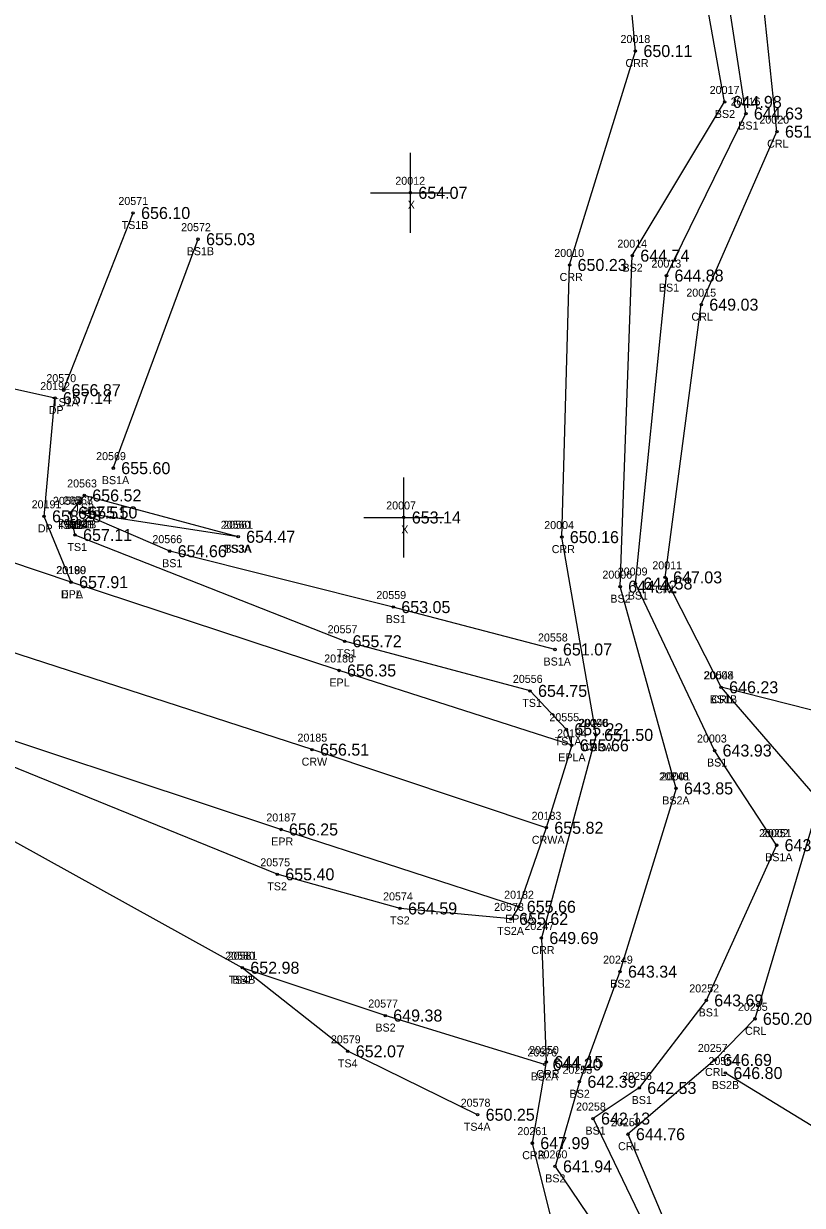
# Model space of a CAD drawing. Extents: x 1655675 to 1657082, y 1004080 to 1005193.
# Drawn here: x 1656296.6 to 1656393.9, y 1004582.5 to 1004730.1 of the extents above; entities that cross this region are included whole.
import ezdxf

# ---------------------------------------------------------------- set-up
doc = ezdxf.new("R2010")
doc.units = 0
for name, color, linetype in [('RD_DTM_BkLn1', 7, 'Continuous'), ('RD_DTM_BkLn2', 7, 'Continuous'), ('RD_DTM_BkLn_txCode', 7, 'Continuous'), ('RD_EX_Driveway', 7, 'Continuous'), ('RD_EX_Driveway_txCode', 7, 'Continuous'), ('RD_EX_H2O', 7, 'Continuous'), ('RD_EX_H2O_txCode', 7, 'Continuous'), ('RD_EX_Misc', 7, 'Continuous'), ('RD_EX_Misc_txCode', 7, 'Continuous'), ('RD_EX_Road', 7, 'Continuous'), ('RD_EX_Road_txCode', 7, 'Continuous'), ('RD_EX_TX_Driveway_ELEV', 7, 'Continuous'), ('RD_EX_TX_H2O_ELEV', 7, 'Continuous'), ('RD_EX_TX_Misc_ELEV', 7, 'Continuous'), ('RD_EX_TX_Road_ELEV', 7, 'Continuous'), ('RD_HC_Survey_ELEV', 7, 'Continuous'), ('RD_HC_Survey_txCode', 7, 'Continuous'), ('RD_SMD_Locator', 7, 'Continuous')]:
    doc.layers.add(name, color=color, linetype=linetype)

msp = doc.modelspace()

# ---------------------------------------------------------------- linework, layer by layer
at = {"layer": 'RD_DTM_BkLn1'}
for points in [[(1656361.94, 1004629.69), (1656332.67, 1004639.45), (1656283.94, 1004655.24), (1656235.41, 1004671.18), (1656186.64, 1004687.32), (1656138.18, 1004703.47), (1656089.58, 1004719.78), (1656041.19, 1004735.88), (1655992.79, 1004752.04), (1655944.27, 1004768.13), (1655895.76, 1004783.85), (1655847.16, 1004799.72), (1655798.63, 1004815.7), (1655750.32, 1004831.65), (1655701.73, 1004847.83)], [(1656364.44, 1004642), (1656365.12, 1004639.99), (1656361.94, 1004629.69), (1656358.5, 1004619.83), (1656357.54, 1004618.31)]]:
    msp.add_lwpolyline(points, dxfattribs=at)
at = {"layer": 'RD_DTM_BkLn2'}
for p, q in [((1656301.62, 1004684.35), (1656310.3, 1004706.48)), ((1656307.82, 1004674.61), (1656318.42, 1004703.21)), ((1656323.43, 1004666.04), (1656303.7, 1004669.08))]:
    msp.add_line(p, q, dxfattribs=at)
for points in [[(1656390.72, 1004627.52), (1656382.97, 1004639.34), (1656373.07, 1004660.2), (1656376.96, 1004698.66), (1656386.88, 1004718.9), (1656381.04, 1004756.9), (1656388.26, 1004792), (1656390.04, 1004832.88), (1656413.02, 1004880.46), (1656422.17, 1004937.24), (1656409.91, 1004961.28), (1656410.07, 1005007.08), (1656404.22, 1005036.82), (1656413.87, 1005085.9), (1656434.1, 1005133.63), (1656432.64, 1005179.28)], [(1656378.15, 1004634.61), (1656371.17, 1004659.81), (1656372.69, 1004701.15), (1656384.23, 1004720.35), (1656377.68, 1004756.93), (1656385.56, 1004794.36), (1656385.16, 1004833.8), (1656408.06, 1004879.84), (1656418.86, 1004937.52), (1656406.15, 1004960.8), (1656407.08, 1005007.2), (1656399.18, 1005037.18), (1656409.22, 1005084.89)], [(1656323.43, 1004666.04), (1656304.2, 1004671.2), (1656302.42, 1004669.03)], [(1656364.44, 1004642), (1656359.91, 1004646.79), (1656336.73, 1004652.99), (1656303.05, 1004666.26), (1656302.42, 1004669.03)], [(1656363.02, 1004651.96), (1656342.82, 1004657.26), (1656314.87, 1004664.24), (1656303.7, 1004669.08)], [(1656357.54, 1004618.31), (1656343.66, 1004619.62), (1656328.32, 1004623.88), (1656279.8, 1004643.61), (1656259.15, 1004647.15), (1656242.07, 1004654.65)], [(1656361.72, 1004600.13), (1656341.81, 1004606.24), (1656323.95, 1004612.21), (1656277.83, 1004637.72), (1656258.21, 1004644.78), (1656241.39, 1004651.73)], [(1656540.84, 1004587.48), (1656491.44, 1004605.3), (1656435.31, 1004628.2), (1656397.73, 1004643.7), (1656383.79, 1004647.24)], [(1656378.15, 1004634.61), (1656371.15, 1004611.72), (1656366.08, 1004597.97), (1656363.03, 1004587.4), (1656375.22, 1004569.39), (1656366.08, 1004537.76), (1656362.3, 1004497.38), (1656381.11, 1004491.46), (1656375.28, 1004468.1), (1656345.39, 1004438.43), (1656334.86, 1004382.95), (1656380.08, 1004353.56), (1656379.77, 1004310.89), (1656346.07, 1004296.22), (1656331.34, 1004265.79), (1656330.54, 1004261.76), (1656332.75, 1004222.72), (1656330.41, 1004184.19), (1656317.27, 1004148.27), (1656308.63, 1004093.1)], [(1656390.72, 1004627.52), (1656381.93, 1004608.13), (1656373.56, 1004597.19), (1656367.78, 1004593.37), (1656379.3, 1004569.5), (1656369.46, 1004537.13), (1656365.12, 1004507.78), (1656384.52, 1004493.19), (1656384.06, 1004470.18), (1656351.72, 1004440.58), (1656340.38, 1004384.23), (1656384.75, 1004357.9), (1656383.63, 1004306.92), (1656350.12, 1004294.84), (1656336.08, 1004262.67), (1656335.68, 1004261.32), (1656338.78, 1004223.26), (1656335.92, 1004183.08), (1656323.69, 1004146.56), (1656313.62, 1004092.92)], [(1656353.36, 1004593.85), (1656337.13, 1004601.77), (1656323.95, 1004612.21)], [(1656501.89, 1004508.05), (1656515.57, 1004543.15), (1656505.12, 1004553.79), (1656467.3, 1004566.38), (1656447.68, 1004569.18), (1656425.18, 1004579.78), (1656399.76, 1004589.64), (1656384.32, 1004599.06)]]:
    msp.add_lwpolyline(points, dxfattribs=at)
at = {"layer": 'RD_EX_Driveway'}
msp.add_lwpolyline([(1656302.55, 1004660.37), (1656299.17, 1004668.59), (1656300.53, 1004683.36), (1656289.45, 1004685.81), (1656288.04, 1004678.95), (1656284.81, 1004671.46), (1656279.15, 1004668.23)], dxfattribs=at)
at = {"layer": 'RD_EX_H2O'}
for points in [[(1656396.09, 1004633.07), (1656383.79, 1004647.24), (1656376.78, 1004660.97), (1656381.31, 1004695.03), (1656390.77, 1004716.64), (1656386.6, 1004756.66), (1656392.47, 1004790.44), (1656395.46, 1004834.73), (1656418.17, 1004880.53), (1656428.48, 1004936.46), (1656416.99, 1004968.14), (1656420.24, 1005011.82), (1656412.2, 1005039.74), (1656428.37, 1005086.9), (1656442.1, 1005137.22), (1656437.49, 1005175.75)], [(1656368.16, 1004641.29), (1656363.88, 1004666), (1656364.85, 1004699.99), (1656373.08, 1004726.71), (1656370.55, 1004754.49), (1656376.9, 1004793.18), (1656381.94, 1004832.3), (1656396.67, 1004890.43), (1656408.46, 1004936.92), (1656401.87, 1004961.79), (1656402.89, 1005007.98), (1656396.57, 1005037.78), (1656403.09, 1005084.85)], [(1656368.16, 1004641.29), (1656361.32, 1004615.92), (1656361.94, 1004600.44), (1656360.19, 1004590.3), (1656364.85, 1004571.61), (1656358.83, 1004539.66), (1656356.39, 1004495.48), (1656374.15, 1004488.29), (1656360.29, 1004470.44), (1656342.68, 1004443.17), (1656328, 1004380.72), (1656370, 1004347.54), (1656371.38, 1004313.92), (1656341.06, 1004297.9), (1656327.33, 1004287.25), (1656316.16, 1004265.33), (1656323.68, 1004217.95), (1656315.99, 1004185.06), (1656305.45, 1004150.63), (1656296.74, 1004101.67)], [(1656396.09, 1004633.07), (1656388.01, 1004605.83), (1656383, 1004600.69), (1656372.14, 1004591.42), (1656381.32, 1004569.61), (1656373.51, 1004535.02), (1656369.64, 1004512.2), (1656394.86, 1004499.5), (1656391.61, 1004464.63), (1656362.04, 1004437.06), (1656349.14, 1004389.09), (1656389.79, 1004361.99), (1656392.68, 1004307.58), (1656360.76, 1004281.14), (1656349.55, 1004259.28), (1656348.46, 1004221.09), (1656343.48, 1004177.61), (1656328.72, 1004142.77), (1656319.4, 1004085.87)]]:
    msp.add_lwpolyline(points, dxfattribs=at)
at = {"layer": 'RD_EX_Misc'}
for p, q in [((1656344.95, 1004704), (1656344.95, 1004714)), ((1656339.95, 1004709), (1656349.95, 1004709)), ((1656344.13, 1004663.45), (1656344.13, 1004673.45)), ((1656339.13, 1004668.45), (1656349.13, 1004668.45))]:
    msp.add_line(p, q, dxfattribs=at)
at = {"layer": 'RD_EX_Road'}
for points in [[(1656365.12, 1004639.99), (1656336.04, 1004649.34), (1656302.55, 1004660.37), (1656279.15, 1004668.23), (1656240.07, 1004681.05), (1656188.23, 1004698.03), (1656166.72, 1004705.51), (1656141.16, 1004714.06), (1656093.11, 1004730.11), (1656044.16, 1004746.75), (1655996.36, 1004762.45), (1655947.2, 1004778.68), (1655899.09, 1004794.03), (1655850.62, 1004809.99), (1655801.91, 1004826.1), (1655753.09, 1004842.31), (1655704.25, 1004858.1)], [(1656358.5, 1004619.83), (1656328.78, 1004629.48), (1656280.77, 1004645.39), (1656247.66, 1004656.11), (1656244.5, 1004656.52), (1656222.03, 1004663.57), (1656217.65, 1004665.96), (1656183.42, 1004677.32), (1656134.59, 1004693.72), (1656086.19, 1004709.75), (1656037.58, 1004726.13), (1655989.57, 1004741.99), (1655940.62, 1004757.88), (1655892.37, 1004773.61), (1655843.48, 1004789.36), (1655805.73, 1004801.4), (1655779.22, 1004810.43), (1655768.8, 1004813.1), (1655744.59, 1004822.13), (1655698.83, 1004837.65)]]:
    msp.add_lwpolyline(points, dxfattribs=at)
at = {"layer": 'RD_SMD_Locator'}
for centre in [(1656373.08, 1004726.71), (1656384.23, 1004720.35), (1656386.88, 1004718.9), (1656390.77, 1004716.64), (1656344.95, 1004709), (1656310.3, 1004706.48), (1656318.42, 1004703.21), (1656372.69, 1004701.15), (1656364.85, 1004699.99), (1656376.96, 1004698.66), (1656381.31, 1004695.03), (1656301.62, 1004684.35), (1656300.53, 1004683.36), (1656307.82, 1004674.61), (1656304.2, 1004671.2), (1656299.17, 1004668.59), (1656302.42, 1004669.03), (1656302.42, 1004669.03), (1656303.7, 1004669.08), (1656303.7, 1004669.08), (1656344.13, 1004668.45), (1656303.05, 1004666.26), (1656323.43, 1004666.04), (1656323.43, 1004666.04), (1656363.88, 1004666), (1656314.87, 1004664.24), (1656376.78, 1004660.97), (1656302.55, 1004660.37), (1656302.55, 1004660.37), (1656371.17, 1004659.81), (1656373.07, 1004660.2), (1656342.82, 1004657.26), (1656336.73, 1004652.99), (1656363.02, 1004651.96), (1656336.04, 1004649.34), (1656359.91, 1004646.79), (1656383.79, 1004647.24), (1656383.79, 1004647.24), (1656364.44, 1004642), (1656365.12, 1004639.99), (1656368.16, 1004641.29), (1656368.16, 1004641.29), (1656332.67, 1004639.45), (1656382.97, 1004639.34), (1656378.15, 1004634.61), (1656378.15, 1004634.61), (1656361.94, 1004629.69), (1656328.78, 1004629.48), (1656390.72, 1004627.52), (1656390.72, 1004627.52), (1656328.32, 1004623.88), (1656343.66, 1004619.62), (1656358.5, 1004619.83), (1656357.54, 1004618.31), (1656361.32, 1004615.92), (1656323.95, 1004612.21), (1656323.95, 1004612.21), (1656371.15, 1004611.72), (1656381.93, 1004608.13), (1656341.81, 1004606.24), (1656388.01, 1004605.83), (1656337.13, 1004601.77), (1656361.72, 1004600.13), (1656361.94, 1004600.44), (1656383, 1004600.69), (1656384.32, 1004599.06), (1656366.08, 1004597.97), (1656373.56, 1004597.19), (1656353.36, 1004593.85), (1656367.78, 1004593.37), (1656372.14, 1004591.42), (1656360.19, 1004590.3), (1656363.03, 1004587.4)]:
    msp.add_circle(centre, 0.15, dxfattribs=at)

# ---------------------------------------------------------------- texts
at = {"layer": 'RD_DTM_BkLn_txCode'}
for s, p in [('20017', (1656382.36, 1004721.35)), ('20016', (1656384.98, 1004719.9)), ('BS2', (1656383, 1004718.35)), ('BS1', (1656385.93, 1004716.9)), ('20571', (1656308.46, 1004707.48)), ('TS1B', (1656308.87, 1004704.48)), ('20572', (1656316.3, 1004704.21)), ('BS1B', (1656317, 1004701.21)), ('20014', (1656370.82, 1004702.15)), ('20013', (1656375.08, 1004699.66)), ('BS2', (1656371.46, 1004699.15)), ('BS1', (1656376.01, 1004696.66)), ('20570', (1656299.46, 1004685.35)), ('TS1A', (1656300.17, 1004682.35)), ('20569', (1656305.68, 1004675.61)), ('20563', (1656302.06, 1004672.2)), ('BS1A', (1656306.39, 1004672.61)), ('20567', (1656301.56, 1004670.08)), ('20568', (1656301.56, 1004670.08)), ('20564', (1656300.28, 1004670.03)), ('20565', (1656300.28, 1004670.03)), ('TS3', (1656302.96, 1004669.2)), ('20562', (1656300.91, 1004667.26)), ('TS3B', (1656300.7, 1004667.03)), ('TS1B', (1656300.98, 1004667.03)), ('BS3B', (1656302, 1004667.08)), ('BS1B', (1656302.28, 1004667.08)), ('20560', (1656321.25, 1004667.04)), ('20561', (1656321.57, 1004667.04)), ('TS1', (1656302.09, 1004664.26)), ('20566', (1656312.71, 1004665.24)), ('TS3A', (1656321.69, 1004664.04)), ('BS3A', (1656321.71, 1004664.04)), ('BS1', (1656313.93, 1004662.24)), ('20006', (1656368.95, 1004660.81)), ('20009', (1656370.87, 1004661.2)), ('20559', (1656340.7, 1004658.26)), ('BS2', (1656369.94, 1004657.81)), ('BS1', (1656372.12, 1004658.2)), ('20557', (1656334.61, 1004653.99)), ('BS1', (1656341.87, 1004655.26)), ('20558', (1656360.9, 1004652.96)), ('TS1', (1656335.77, 1004650.99)), ('BS1A', (1656361.59, 1004649.96)), ('20544', (1656381.67, 1004648.24)), ('20556', (1656357.76, 1004647.79)), ('BS1B', (1656382.37, 1004645.24)), ('TS1', (1656358.94, 1004644.79)), ('20555', (1656362.32, 1004643)), ('TS1A', (1656362.99, 1004640)), ('20003', (1656380.77, 1004640.34)), ('BS1', (1656382.02, 1004637.34)), ('20248', (1656376.03, 1004635.61)), ('20001', (1656376.23, 1004635.61)), ('BS2A', (1656376.43, 1004632.61)), ('BS2A', (1656376.43, 1004632.61)), ('20002', (1656388.52, 1004628.52)), ('20251', (1656388.88, 1004628.52)), ('20575', (1656326.2, 1004624.88)), ('BS1A', (1656389.29, 1004625.52)), ('BS1A', (1656389.29, 1004625.52)), ('TS2', (1656327.07, 1004621.88)), ('20574', (1656341.54, 1004620.62)), ('20573', (1656355.42, 1004619.31)), ('TS2', (1656342.41, 1004617.62)), ('TS2A', (1656355.8, 1004616.31)), ('20580', (1656321.8, 1004613.21)), ('20581', (1656322.12, 1004613.21)), ('20249', (1656369.03, 1004612.72)), ('TS4B', (1656322.24, 1004610.21)), ('BS2', (1656322.72, 1004610.21)), ('BS2', (1656369.92, 1004609.72)), ('20252', (1656379.81, 1004609.13)), ('20577', (1656339.69, 1004607.24)), ('BS1', (1656380.98, 1004606.13)), ('BS2', (1656340.58, 1004604.24)), ('20579', (1656335.02, 1004602.77)), ('20576', (1656359.57, 1004601.13)), ('TS4', (1656335.89, 1004599.77)), ('20554', (1656382.2, 1004600.06)), ('BS2A', (1656360, 1004598.13)), ('20253', (1656363.96, 1004598.97)), ('20256', (1656371.42, 1004598.19)), ('BS2B', (1656382.62, 1004597.06)), ('20578', (1656351.24, 1004594.85)), ('BS2', (1656364.85, 1004595.97)), ('BS1', (1656372.61, 1004595.19)), ('20258', (1656365.66, 1004594.37)), ('TS4A', (1656351.63, 1004591.85)), ('BS1', (1656366.83, 1004591.37)), ('20260', (1656360.85, 1004588.4)), ('BS2', (1656361.8, 1004585.4))]:
    msp.add_text(s, height=1, dxfattribs=at).set_placement(p)
at = {"layer": 'RD_EX_Driveway_txCode'}
for s, p in [('20192', (1656298.69, 1004684.36)), ('DP', (1656299.75, 1004681.36)), ('20191', (1656297.62, 1004669.59)), ('DP', (1656298.39, 1004666.59)), ('20190', (1656300.68, 1004661.37)), ('DPA', (1656301.28, 1004658.37))]:
    msp.add_text(s, height=1, dxfattribs=at).set_placement(p)
at = {"layer": 'RD_EX_H2O_txCode'}
for s, p in [('20018', (1656371.21, 1004727.71)), ('CRR', (1656371.83, 1004724.71)), ('20020', (1656388.57, 1004717.64)), ('CRL', (1656389.54, 1004714.64)), ('20010', (1656362.94, 1004700.99)), ('CRR', (1656363.6, 1004697.99)), ('20015', (1656379.44, 1004696.03)), ('CRL', (1656380.08, 1004693.03)), ('20004', (1656361.68, 1004667)), ('CRR', (1656362.62, 1004664)), ('20011', (1656375.19, 1004661.97)), ('CRL', (1656375.55, 1004658.97)), ('20008', (1656381.59, 1004648.24)), ('CRL', (1656382.56, 1004645.24)), ('20000', (1656365.92, 1004642.29)), ('20246', (1656366.02, 1004642.29)), ('CRRA', (1656366.42, 1004639.29)), ('CRRA', (1656366.42, 1004639.29)), ('20247', (1656359.2, 1004616.92)), ('CRR', (1656360.07, 1004613.92)), ('20255', (1656385.89, 1004606.83)), ('CRL', (1656386.78, 1004603.83)), ('20250', (1656359.78, 1004601.44)), ('20257', (1656380.88, 1004601.69)), ('CRR', (1656360.69, 1004598.44)), ('CRL', (1656381.77, 1004598.69)), ('20259', (1656370.02, 1004592.42)), ('20261', (1656358.33, 1004591.3)), ('CRL', (1656370.91, 1004589.42)), ('CRR', (1656358.93, 1004588.3))]:
    msp.add_text(s, height=1, dxfattribs=at).set_placement(p)
at = {"layer": 'RD_EX_Misc_txCode'}
for s, p in [('20012', (1656343.07, 1004710)), ('X', (1656344.63, 1004707)), ('20007', (1656341.93, 1004669.45)), ('X', (1656343.81, 1004666.45))]:
    msp.add_text(s, height=1, dxfattribs=at).set_placement(p)
at = {"layer": 'RD_EX_Road_txCode'}
for s, p in [('20189', (1656300.72, 1004661.37)), ('EPL', (1656301.35, 1004658.37)), ('20186', (1656334.18, 1004650.34)), ('EPL', (1656334.83, 1004647.34)), ('20184', (1656363.29, 1004640.99)), ('EPLA', (1656363.43, 1004637.99)), ('20187', (1656326.95, 1004630.48)), ('EPR', (1656327.56, 1004627.48)), ('20182', (1656356.67, 1004620.83)), ('EPRA', (1656356.79, 1004617.83))]:
    msp.add_text(s, height=1, dxfattribs=at).set_placement(p)
at = {"layer": 'RD_EX_TX_Driveway_ELEV'}
for s, p in [('657.14', (1656301.53, 1004682.61)), ('658.28', (1656300.17, 1004667.84)), ('657.91', (1656303.55, 1004659.62))]:
    msp.add_text(s, height=1.5, dxfattribs=at).set_placement(p)
at = {"layer": 'RD_EX_TX_H2O_ELEV'}
for s, p in [('650.11', (1656374.08, 1004725.96)), ('651.40', (1656391.77, 1004715.89)), ('650.23', (1656365.85, 1004699.24)), ('649.03', (1656382.31, 1004694.28)), ('650.16', (1656364.88, 1004665.25)), ('647.03', (1656377.78, 1004660.22)), ('646.23', (1656384.79, 1004646.49)), ('651.50', (1656369.16, 1004640.54)), ('651.50', (1656369.16, 1004640.54)), ('649.69', (1656362.32, 1004615.17)), ('650.20', (1656389.01, 1004605.08)), ('644.15', (1656362.94, 1004599.69)), ('646.69', (1656384, 1004599.94)), ('644.76', (1656373.14, 1004590.67)), ('647.99', (1656361.19, 1004589.55))]:
    msp.add_text(s, height=1.5, dxfattribs=at).set_placement(p)
at = {"layer": 'RD_EX_TX_Misc_ELEV'}
for s, p in [('644.98', (1656385.23, 1004719.6)), ('644.63', (1656387.88, 1004718.15)), ('654.07', (1656345.95, 1004708.25)), ('656.10', (1656311.3, 1004705.73)), ('655.03', (1656319.42, 1004702.46)), ('644.74', (1656373.69, 1004700.4)), ('644.88', (1656377.96, 1004697.91)), ('656.87', (1656302.62, 1004683.6)), ('655.60', (1656308.82, 1004673.86)), ('656.52', (1656305.2, 1004670.45)), ('657.51', (1656303.42, 1004668.28)), ('657.51', (1656303.42, 1004668.28)), ('655.50', (1656304.7, 1004668.33)), ('655.50', (1656304.7, 1004668.33)), ('653.14', (1656345.13, 1004667.7)), ('657.11', (1656304.05, 1004665.51)), ('654.47', (1656324.43, 1004665.29)), ('654.47', (1656324.43, 1004665.29)), ('654.66', (1656315.87, 1004663.49)), ('644.58', (1656374.07, 1004659.45)), ('644.42', (1656372.17, 1004659.06)), ('653.05', (1656343.82, 1004656.51)), ('655.72', (1656337.73, 1004652.24)), ('651.07', (1656364.02, 1004651.21)), ('654.75', (1656360.91, 1004646.04)), ('646.23', (1656384.79, 1004646.49)), ('655.22', (1656365.44, 1004641.25)), ('643.93', (1656383.97, 1004638.59)), ('643.85', (1656379.15, 1004633.86)), ('643.85', (1656379.15, 1004633.86)), ('643.93', (1656391.72, 1004626.77)), ('643.93', (1656391.72, 1004626.77)), ('655.40', (1656329.32, 1004623.13)), ('654.59', (1656344.66, 1004618.87)), ('655.62', (1656358.54, 1004617.56)), ('652.98', (1656324.95, 1004611.46)), ('652.98', (1656324.95, 1004611.46)), ('643.34', (1656372.15, 1004610.97)), ('643.69', (1656382.93, 1004607.38)), ('649.38', (1656342.81, 1004605.49)), ('652.07', (1656338.13, 1004601.02)), ('644.20', (1656362.72, 1004599.38)), ('646.80', (1656385.32, 1004598.31)), ('642.39', (1656367.08, 1004597.22)), ('642.53', (1656374.56, 1004596.44)), ('650.25', (1656354.36, 1004593.1)), ('642.13', (1656368.78, 1004592.62)), ('641.94', (1656364.03, 1004586.65))]:
    msp.add_text(s, height=1.5, dxfattribs=at).set_placement(p)
at = {"layer": 'RD_EX_TX_Road_ELEV'}
for s, p in [('657.91', (1656303.55, 1004659.62)), ('656.35', (1656337.04, 1004648.59)), ('655.66', (1656366.12, 1004639.24)), ('656.25', (1656329.78, 1004628.73)), ('655.66', (1656359.5, 1004619.08))]:
    msp.add_text(s, height=1.5, dxfattribs=at).set_placement(p)
at = {"layer": 'RD_HC_Survey_ELEV'}
for s, p in [('656.51', (1656333.67, 1004638.7)), ('655.82', (1656362.94, 1004628.94))]:
    msp.add_text(s, height=1.5, dxfattribs=at).set_placement(p)
at = {"layer": 'RD_HC_Survey_txCode'}
for s, p in [('20185', (1656330.84, 1004640.45)), ('CRW', (1656331.36, 1004637.45)), ('20183', (1656360.1, 1004630.69)), ('CRWA', (1656360.13, 1004627.69))]:
    msp.add_text(s, height=1, dxfattribs=at).set_placement(p)

doc.saveas('drawing.dxf')
